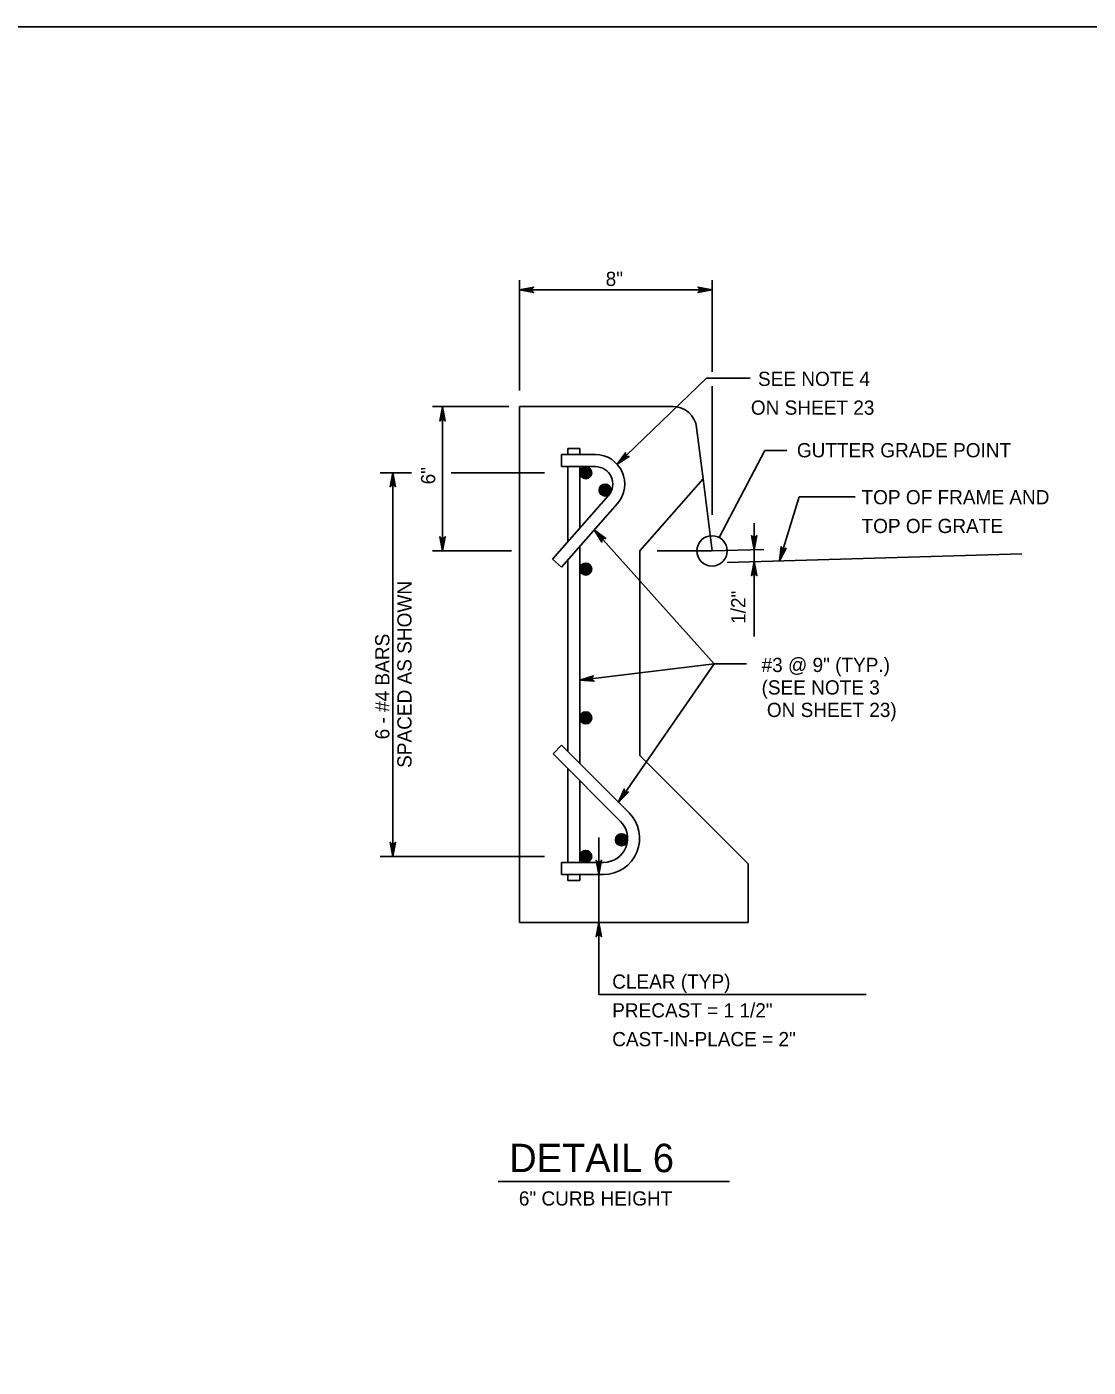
# Model space of a CAD drawing. Extents: x 2087776 to 2104538, y 970919 to 982612.
# Drawn here: x 2094157 to 2094893, y 971891 to 972819 of the extents above; entities that cross this region are included whole.
import ezdxf

# ---------------------------------------------------------------- set-up
doc = ezdxf.new("R2010")
doc.units = 0
doc.layers.add('1', color=7, linetype='Continuous')

msp = doc.modelspace()

# ---------------------------------------------------------------- linework, layer by layer
at = {"layer": '1'}
for p, q in [((2094498.72, 972643.41), (2094498.72, 972567.09)), ((2094632.06, 972643.41), (2094632.06, 972580.08)), ((2094498.72, 972636.85), (2094632.06, 972636.85)), ((2094632.06, 972570.04), (2094632.06, 972481)), ((2094438.47, 972556.01), (2094491.38, 972556.01)), ((2094445.35, 972456.01), (2094445.35, 972556.01)), ((2094498.72, 972198.65), (2094498.72, 972556.01)), ((2094604.85, 972556.01), (2094498.72, 972556.01)), ((2094625.81, 972506.01), (2094621.39, 972541.41)), ((2094551.28, 972522.68), (2094527.88, 972522.68)), ((2094527.88, 972514.35), (2094527.88, 972522.68)), ((2094540.38, 972526.85), (2094532.05, 972526.85)), ((2094532.05, 972522.68), (2094532.05, 972526.85)), ((2094540.38, 972522.68), (2094540.38, 972526.85)), ((2094636.94, 972465.3), (2094668.65, 972525.63)), ((2094668.65, 972525.63), (2094683.82, 972525.63)), ((2094402.1, 972510.18), (2094423.93, 972510.18)), ((2094410.94, 972510.18), (2094410.94, 972244.47)), ((2094451.41, 972510.18), (2094515.9, 972510.18)), ((2094551.3, 972514.35), (2094527.88, 972514.35)), ((2094532.05, 972462.12), (2094532.05, 972514.35)), ((2094540.38, 972471.64), (2094540.38, 972514.35)), ((2094625.81, 972506.01), (2094582.06, 972456.01)), ((2094632.06, 972456.01), (2094625.81, 972506.01)), ((2094560.33, 972494.44), (2094521.61, 972450.19)), ((2094692.5, 972493.5), (2094678.76, 972449.1)), ((2094692.5, 972493.5), (2094731.15, 972493.5)), ((2094566.59, 972488.94), (2094527.88, 972444.7)), ((2094661.28, 972475.2), (2094661.28, 972396.67)), ((2094550.5, 972470.56), (2094633.54, 972377.82)), ((2094438.47, 972456.01), (2094493.09, 972456.01)), ((2094540.38, 972308.87), (2094540.38, 972458.99)), ((2094582.06, 972314.33), (2094582.06, 972456.01)), ((2094594.13, 972456.01), (2094632.06, 972456.01)), ((2094667.91, 972457.06), (2094632.06, 972456.01)), ((2094632.06, 972456.01), (2094632.06, 972456.01)), ((2094846.64, 972454.03), (2094642.6, 972448.03)), ((2094527.88, 972444.7), (2094521.61, 972450.19)), ((2094532.05, 972317.2), (2094532.05, 972449.47)), ((2094633.54, 972377.82), (2094540.38, 972366.42)), ((2094567.24, 972282.01), (2094633.54, 972377.82)), ((2094633.54, 972377.82), (2094655.85, 972377.82)), ((2094527.88, 972321.37), (2094521.99, 972315.48)), ((2094568.74, 972268.73), (2094521.99, 972315.48)), ((2094574.59, 972274.65), (2094527.88, 972321.37)), ((2094657.06, 972239.33), (2094582.06, 972314.33)), ((2094532.05, 972240.31), (2094532.05, 972305.42)), ((2094540.38, 972240.31), (2094540.38, 972297.09)), ((2094553.58, 972257.52), (2094553.58, 972148.76)), ((2094402.1, 972244.47), (2094515.9, 972244.47)), ((2094556.96, 972240.31), (2094527.88, 972240.31)), ((2094527.88, 972231.98), (2094527.88, 972240.31)), ((2094556.92, 972231.98), (2094527.88, 972231.98)), ((2094532.05, 972227.81), (2094532.05, 972231.98)), ((2094540.38, 972227.81), (2094540.38, 972231.98)), ((2094657.06, 972198.65), (2094657.06, 972239.33)), ((2094532.05, 972227.81), (2094540.38, 972227.81)), ((2094657.06, 972198.65), (2094498.72, 972198.65)), ((2094553.58, 972148.76), (2094738.83, 972148.76)), ((2094484, 972019.4), (2094644.24, 972019.4))]:
    msp.add_line(p, q, dxfattribs=at)
for points in [[(2096000.74, 970968.55), (2096000.74, 972818.94), (2093422, 972818.94), (2093422, 970968.55), (2096000.74, 970968.55), (2096000.74, 971055.03), (2095344.57, 971055.03), (2095344.57, 971267.23), (2096000.74, 971267.23), (2096000.74, 971362.25), (2095344.57, 971362.25), (2095344.57, 970968.55), (2095603.11, 970968.55), (2095603.11, 971055.03), (2095603.11, 970968.55), (2095855.73, 970968.55), (2095855.73, 971055.03), (2095855.73, 971014.62), (2096000.74, 971014.62)], [(2094498.72, 972636.85), (2094508.5, 972638.68), (2094508.13, 972638.42), (2094507.75, 972638.16), (2094507.55, 972637.83), (2094507.36, 972637.5), (2094507.3, 972637.18), (2094507.25, 972636.85), (2094507.3, 972636.52), (2094507.36, 972636.19), (2094507.55, 972635.86), (2094507.75, 972635.54), (2094508.13, 972635.27), (2094508.5, 972635.01), (2094498.72, 972636.85), (2094508.13, 972635.27), (2094507.75, 972635.54), (2094498.72, 972636.85), (2094507.55, 972635.86), (2094507.36, 972636.19), (2094498.72, 972636.85), (2094507.3, 972636.52), (2094507.25, 972636.85), (2094498.72, 972636.85), (2094507.3, 972637.18), (2094507.36, 972637.5), (2094498.72, 972636.85), (2094507.55, 972637.83), (2094507.75, 972638.16), (2094498.72, 972636.85), (2094508.13, 972638.42)], [(2094632.06, 972636.85), (2094622.27, 972635.01), (2094622.65, 972635.27), (2094623.03, 972635.54), (2094623.22, 972635.86), (2094623.41, 972636.19), (2094623.47, 972636.52), (2094623.53, 972636.85), (2094623.47, 972637.18), (2094623.41, 972637.5), (2094623.22, 972637.83), (2094623.03, 972638.16), (2094622.65, 972638.42), (2094622.27, 972638.68), (2094632.06, 972636.85), (2094622.65, 972638.42), (2094623.03, 972638.16), (2094632.06, 972636.85), (2094623.22, 972637.83), (2094623.41, 972637.5), (2094632.06, 972636.85), (2094623.47, 972637.18), (2094623.53, 972636.85), (2094632.06, 972636.85), (2094623.47, 972636.52), (2094623.41, 972636.19), (2094632.06, 972636.85), (2094623.22, 972635.86), (2094623.03, 972635.54), (2094632.06, 972636.85), (2094622.65, 972635.27)], [(2094566.37, 972515.97), (2094628.15, 972575.56), (2094658.5, 972575.56)], [(2094445.35, 972555.69), (2094447.19, 972545.9), (2094446.93, 972546.28), (2094446.67, 972546.66), (2094446.34, 972546.85), (2094446.01, 972547.05), (2094445.68, 972547.1), (2094445.35, 972547.16), (2094445.03, 972547.1), (2094444.7, 972547.05), (2094444.37, 972546.85), (2094444.04, 972546.66), (2094443.78, 972546.28), (2094443.52, 972545.9), (2094445.35, 972555.69), (2094443.78, 972546.28), (2094444.04, 972546.66), (2094445.35, 972555.69), (2094444.37, 972546.85), (2094444.7, 972547.05), (2094445.35, 972555.69), (2094445.03, 972547.1), (2094445.35, 972547.16), (2094445.35, 972555.69), (2094445.68, 972547.1), (2094446.01, 972547.05), (2094445.35, 972555.69), (2094446.34, 972546.85), (2094446.67, 972546.66), (2094445.35, 972555.69), (2094446.93, 972546.28)], [(2094566.37, 972515.97), (2094572.1, 972524.02), (2094572.01, 972523.57), (2094571.92, 972523.13), (2094572.01, 972522.76), (2094572.1, 972522.39), (2094572.28, 972522.12), (2094572.47, 972521.84), (2094572.73, 972521.65), (2094573, 972521.45), (2094573.36, 972521.35), (2094573.73, 972521.25), (2094574.18, 972521.32), (2094574.63, 972521.4), (2094566.37, 972515.97), (2094574.18, 972521.32), (2094573.73, 972521.25), (2094566.37, 972515.97), (2094573.36, 972521.35), (2094573, 972521.45), (2094566.37, 972515.97), (2094572.73, 972521.65), (2094572.47, 972521.84), (2094566.37, 972515.97), (2094572.28, 972522.12), (2094572.1, 972522.39), (2094566.37, 972515.97), (2094572.01, 972522.76), (2094571.92, 972523.13), (2094566.37, 972515.97), (2094572.01, 972523.57)], [(2094410.94, 972510.18), (2094412.77, 972500.39), (2094412.51, 972500.77), (2094412.25, 972501.14), (2094411.92, 972501.34), (2094411.6, 972501.53), (2094411.27, 972501.59), (2094410.94, 972501.65), (2094410.61, 972501.59), (2094410.28, 972501.53), (2094409.96, 972501.34), (2094409.63, 972501.14), (2094409.37, 972500.77), (2094409.1, 972500.39), (2094410.94, 972510.18), (2094409.37, 972500.77), (2094409.63, 972501.14), (2094410.94, 972510.18), (2094409.96, 972501.34), (2094410.28, 972501.53), (2094410.94, 972510.18), (2094410.61, 972501.59), (2094410.94, 972501.65), (2094410.94, 972510.18), (2094411.27, 972501.59), (2094411.6, 972501.53), (2094410.94, 972510.18), (2094411.92, 972501.34), (2094412.25, 972501.14), (2094410.94, 972510.18), (2094412.51, 972500.77)], [(2094445.35, 972456.01), (2094443.52, 972465.79), (2094443.78, 972465.41), (2094444.04, 972465.04), (2094444.37, 972464.84), (2094444.7, 972464.65), (2094445.03, 972464.59), (2094445.35, 972464.54), (2094445.68, 972464.59), (2094446.01, 972464.65), (2094446.34, 972464.84), (2094446.67, 972465.04), (2094446.93, 972465.41), (2094447.19, 972465.79), (2094445.35, 972456.01), (2094446.93, 972465.41), (2094446.67, 972465.04), (2094445.35, 972456.01), (2094446.34, 972464.84), (2094446.01, 972464.65), (2094445.35, 972456.01), (2094445.68, 972464.59), (2094445.35, 972464.54), (2094445.35, 972456.01), (2094445.03, 972464.59), (2094444.7, 972464.65), (2094445.35, 972456.01), (2094444.37, 972464.84), (2094444.04, 972465.04), (2094445.35, 972456.01), (2094443.78, 972465.41)], [(2094550.5, 972470.56), (2094558.46, 972464.57), (2094558.01, 972464.67), (2094557.56, 972464.77), (2094557.19, 972464.7), (2094556.82, 972464.62), (2094556.54, 972464.44), (2094556.26, 972464.26), (2094556.05, 972464), (2094555.85, 972463.73), (2094555.74, 972463.37), (2094555.62, 972463), (2094555.69, 972462.55), (2094555.75, 972462.1), (2094550.5, 972470.56), (2094555.69, 972462.55), (2094555.62, 972463), (2094550.5, 972470.56), (2094555.74, 972463.37), (2094555.85, 972463.73), (2094550.5, 972470.56), (2094556.05, 972464), (2094556.26, 972464.26), (2094550.5, 972470.56), (2094556.54, 972464.44), (2094556.82, 972464.62), (2094550.5, 972470.56), (2094557.19, 972464.7), (2094557.56, 972464.77), (2094550.5, 972470.56), (2094558.01, 972464.67)], [(2094661.28, 972456.86), (2094659.45, 972466.65), (2094659.71, 972466.27), (2094659.97, 972465.9), (2094660.3, 972465.7), (2094660.62, 972465.51), (2094660.95, 972465.45), (2094661.28, 972465.39), (2094661.61, 972465.45), (2094661.94, 972465.51), (2094662.26, 972465.7), (2094662.59, 972465.9), (2094662.85, 972466.27), (2094663.12, 972466.65), (2094661.28, 972456.86), (2094662.85, 972466.27), (2094662.59, 972465.9), (2094661.28, 972456.86), (2094662.26, 972465.7), (2094661.94, 972465.51), (2094661.28, 972456.86), (2094661.61, 972465.45), (2094661.28, 972465.39), (2094661.28, 972456.86), (2094660.95, 972465.45), (2094660.62, 972465.51), (2094661.28, 972456.86), (2094660.3, 972465.7), (2094659.97, 972465.9), (2094661.28, 972456.86), (2094659.71, 972466.27)], [(2094678.76, 972449.1), (2094679.9, 972458.99), (2094680.04, 972458.55), (2094680.18, 972458.11), (2094680.43, 972457.83), (2094680.69, 972457.55), (2094680.99, 972457.4), (2094681.28, 972457.24), (2094681.61, 972457.2), (2094681.94, 972457.16), (2094682.32, 972457.25), (2094682.69, 972457.34), (2094683.05, 972457.62), (2094683.41, 972457.9), (2094678.76, 972449.1), (2094683.05, 972457.62), (2094682.69, 972457.34), (2094678.76, 972449.1), (2094682.32, 972457.25), (2094681.94, 972457.16), (2094678.76, 972449.1), (2094681.61, 972457.2), (2094681.28, 972457.24), (2094678.76, 972449.1), (2094680.99, 972457.4), (2094680.69, 972457.55), (2094678.76, 972449.1), (2094680.43, 972457.83), (2094680.18, 972458.11), (2094678.76, 972449.1), (2094680.04, 972458.55)], [(2094661.28, 972448.58), (2094663.12, 972438.8), (2094662.85, 972439.17), (2094662.59, 972439.55), (2094662.26, 972439.74), (2094661.94, 972439.94), (2094661.61, 972440), (2094661.28, 972440.05), (2094660.95, 972440), (2094660.62, 972439.94), (2094660.3, 972439.74), (2094659.97, 972439.55), (2094659.71, 972439.17), (2094659.45, 972438.8), (2094661.28, 972448.58), (2094659.71, 972439.17), (2094659.97, 972439.55), (2094661.28, 972448.58), (2094660.3, 972439.74), (2094660.62, 972439.94), (2094661.28, 972448.58), (2094660.95, 972440), (2094661.28, 972440.05), (2094661.28, 972448.58), (2094661.61, 972440), (2094661.94, 972439.94), (2094661.28, 972448.58), (2094662.26, 972439.74), (2094662.59, 972439.55), (2094661.28, 972448.58), (2094662.85, 972439.17)], [(2094540.38, 972366.42), (2094549.87, 972369.43), (2094549.52, 972369.12), (2094549.18, 972368.82), (2094549.03, 972368.47), (2094548.88, 972368.12), (2094548.86, 972367.79), (2094548.84, 972367.45), (2094548.94, 972367.13), (2094549.04, 972366.82), (2094549.27, 972366.51), (2094549.5, 972366.21), (2094549.91, 972366), (2094550.31, 972365.78), (2094540.38, 972366.42), (2094549.91, 972366), (2094549.5, 972366.21), (2094540.38, 972366.42), (2094549.27, 972366.51), (2094549.04, 972366.82), (2094540.38, 972366.42), (2094548.94, 972367.13), (2094548.84, 972367.45), (2094540.38, 972366.42), (2094548.86, 972367.79), (2094548.88, 972368.12), (2094540.38, 972366.42), (2094549.03, 972368.47), (2094549.18, 972368.82), (2094540.38, 972366.42), (2094549.52, 972369.12)], [(2094567.24, 972282.01), (2094571.26, 972291.11), (2094571.26, 972290.65), (2094571.27, 972290.2), (2094571.43, 972289.85), (2094571.59, 972289.5), (2094571.83, 972289.27), (2094572.07, 972289.04), (2094572.37, 972288.9), (2094572.67, 972288.76), (2094573.05, 972288.74), (2094573.43, 972288.71), (2094573.86, 972288.87), (2094574.29, 972289.04), (2094567.24, 972282.01), (2094573.86, 972288.87), (2094573.43, 972288.71), (2094567.24, 972282.01), (2094573.05, 972288.74), (2094572.67, 972288.76), (2094567.24, 972282.01), (2094572.37, 972288.9), (2094572.07, 972289.04), (2094567.24, 972282.01), (2094571.83, 972289.27), (2094571.59, 972289.5), (2094567.24, 972282.01), (2094571.43, 972289.85), (2094571.27, 972290.2), (2094567.24, 972282.01), (2094571.26, 972290.65)], [(2094410.94, 972244.47), (2094409.1, 972254.26), (2094409.37, 972253.88), (2094409.63, 972253.5), (2094409.96, 972253.31), (2094410.28, 972253.12), (2094410.61, 972253.06), (2094410.94, 972253), (2094411.27, 972253.06), (2094411.6, 972253.12), (2094411.92, 972253.31), (2094412.25, 972253.5), (2094412.51, 972253.88), (2094412.77, 972254.26), (2094410.94, 972244.47), (2094412.51, 972253.88), (2094412.25, 972253.5), (2094410.94, 972244.47), (2094411.92, 972253.31), (2094411.6, 972253.12), (2094410.94, 972244.47), (2094411.27, 972253.06), (2094410.94, 972253), (2094410.94, 972244.47), (2094410.61, 972253.06), (2094410.28, 972253.12), (2094410.94, 972244.47), (2094409.96, 972253.31), (2094409.63, 972253.5), (2094410.94, 972244.47), (2094409.37, 972253.88)], [(2094553.58, 972231.98), (2094551.75, 972241.76), (2094552.01, 972241.38), (2094552.27, 972241.01), (2094552.6, 972240.81), (2094552.93, 972240.62), (2094553.26, 972240.56), (2094553.58, 972240.51), (2094553.91, 972240.56), (2094554.24, 972240.62), (2094554.57, 972240.81), (2094554.9, 972241.01), (2094555.16, 972241.38), (2094555.42, 972241.76), (2094553.58, 972231.98), (2094555.16, 972241.38), (2094554.9, 972241.01), (2094553.58, 972231.98), (2094554.57, 972240.81), (2094554.24, 972240.62), (2094553.58, 972231.98), (2094553.91, 972240.56), (2094553.58, 972240.51), (2094553.58, 972231.98), (2094553.26, 972240.56), (2094552.93, 972240.62), (2094553.58, 972231.98), (2094552.6, 972240.81), (2094552.27, 972241.01), (2094553.58, 972231.98), (2094552.01, 972241.38)], [(2094553.58, 972198.65), (2094551.75, 972188.86), (2094552.01, 972189.24), (2094552.27, 972189.61), (2094552.6, 972189.81), (2094552.93, 972190), (2094553.26, 972190.06), (2094553.58, 972190.11), (2094553.91, 972190.06), (2094554.24, 972190), (2094554.57, 972189.81), (2094554.9, 972189.61), (2094555.16, 972189.24), (2094555.42, 972188.86), (2094553.58, 972198.65), (2094555.16, 972189.24), (2094554.9, 972189.61), (2094553.58, 972198.65), (2094554.57, 972189.81), (2094554.24, 972190), (2094553.58, 972198.65), (2094553.91, 972190.06), (2094553.58, 972190.11), (2094553.58, 972198.65), (2094553.26, 972190.06), (2094552.93, 972190), (2094553.58, 972198.65), (2094552.6, 972189.81), (2094552.27, 972189.61), (2094553.58, 972198.65), (2094552.01, 972189.24)]]:
    msp.add_lwpolyline(points, dxfattribs=at)
for centre, radius in [((2094544.54, 972510.18), 4.17), ((2094544.54, 972510.18), 3.87), ((2094544.54, 972510.18), 3.58), ((2094544.54, 972510.18), 3.28), ((2094544.54, 972510.18), 2.98), ((2094544.54, 972510.18), 2.69), ((2094544.54, 972510.18), 2.39), ((2094544.54, 972510.18), 2.1), ((2094544.54, 972510.18), 1.8), ((2094544.54, 972510.18), 1.5), ((2094544.54, 972510.18), 1.21), ((2094544.54, 972510.18), 0.912), ((2094544.54, 972510.18), 0.616), ((2094544.54, 972510.18), 0.32), ((2094557.92, 972498.15), 4.17), ((2094557.92, 972498.15), 3.87), ((2094557.92, 972498.15), 3.58), ((2094557.92, 972498.15), 3.28), ((2094557.92, 972498.15), 2.98), ((2094557.92, 972498.15), 2.69), ((2094557.92, 972498.15), 2.39), ((2094557.92, 972498.15), 2.1), ((2094557.92, 972498.15), 1.8), ((2094557.92, 972498.15), 1.5), ((2094557.92, 972498.15), 1.21), ((2094557.92, 972498.15), 0.912), ((2094557.92, 972498.15), 0.616), ((2094557.92, 972498.15), 0.32), ((2094632.06, 972456.01), 10.5), ((2094544.54, 972443.44), 4.17), ((2094544.54, 972443.44), 3.87), ((2094544.54, 972443.44), 3.58), ((2094544.54, 972443.44), 3.28), ((2094544.54, 972443.44), 2.98), ((2094544.54, 972443.44), 2.69), ((2094544.54, 972443.44), 2.39), ((2094544.54, 972443.44), 2.1), ((2094544.54, 972443.44), 1.8), ((2094544.54, 972443.44), 1.5), ((2094544.54, 972443.44), 1.21), ((2094544.54, 972443.44), 0.912), ((2094544.54, 972443.44), 0.616), ((2094544.54, 972443.44), 0.32), ((2094544.54, 972340.38), 4.17), ((2094544.54, 972340.38), 3.87), ((2094544.54, 972340.38), 3.58), ((2094544.54, 972340.38), 3.28), ((2094544.54, 972340.38), 2.98), ((2094544.54, 972340.38), 2.69), ((2094544.54, 972340.38), 2.39), ((2094544.54, 972340.38), 2.1), ((2094544.54, 972340.38), 1.8), ((2094544.54, 972340.38), 1.5), ((2094544.54, 972340.38), 1.21), ((2094544.54, 972340.38), 0.912), ((2094544.54, 972340.38), 0.616), ((2094544.54, 972340.38), 0.32), ((2094569.36, 972255.98), 4.17), ((2094569.36, 972255.98), 3.87), ((2094569.36, 972255.98), 3.58), ((2094569.36, 972255.98), 3.28), ((2094569.36, 972255.98), 2.98), ((2094569.36, 972255.98), 2.69), ((2094569.36, 972255.98), 2.39), ((2094569.36, 972255.98), 2.1), ((2094544.54, 972244.47), 4.17), ((2094569.36, 972255.98), 1.8), ((2094569.36, 972255.98), 1.5), ((2094569.36, 972255.98), 1.21), ((2094569.36, 972255.98), 0.912), ((2094569.36, 972255.98), 0.616), ((2094569.36, 972255.98), 0.32), ((2094544.54, 972244.47), 3.87), ((2094544.54, 972244.47), 3.58), ((2094544.54, 972244.47), 3.28), ((2094544.54, 972244.47), 2.98), ((2094544.54, 972244.47), 2.69), ((2094544.54, 972244.47), 2.39), ((2094544.54, 972244.47), 2.1), ((2094544.54, 972244.47), 1.8), ((2094544.54, 972244.47), 1.5), ((2094544.54, 972244.47), 1.21), ((2094544.54, 972244.47), 0.912), ((2094544.54, 972244.47), 0.616), ((2094544.54, 972244.47), 0.32)]:
    msp.add_circle(centre, radius, dxfattribs=at)
for centre, radius, start, end in [((2094604.85, 972539.34), 16.67, 7.12184, 90), ((2094551.28, 972502.34), 20.34, 318.81225, 90), ((2094551.3, 972502.35), 12, 318.81225, 90), ((2094556.92, 972256.98), 25, 270, 45), ((2094556.96, 972256.96), 16.65, 270, 45)]:
    msp.add_arc(centre, radius, start, end, dxfattribs=at)

# ---------------------------------------------------------------- texts
for s, height, rotation, p in [('8"', 9.843, 360, (2094558.38, 972639.46)), ('6"', 9.843, 90, (2094440.28, 972502.08)), ('SPACED AS SHOWN', 9.8425, 90, (2094423.88, 972305.76)), ('1/2"', 9.843, 90, (2094655.16, 972405.45)), ('6 - #4 BARS', 9.8425, 90, (2094408.53, 972325.49))]:
    msp.add_text(s, height=height, rotation=rotation, dxfattribs=at).set_placement(p)
for s, height, p in [('SEE NOTE 4', 9.843, (2094663.89, 972570.24)), ('ON SHEET 23', 9.8425, (2094658.96, 972550.32)), ('GUTTER GRADE POINT', 9.8425, (2094690.84, 972520.82)), ('TOP OF FRAME AND', 9.8425, (2094735.64, 972488.29)), ('TOP OF GRATE', 9.8425, (2094735.64, 972468.37)), ('#3 @ 9" (TYP.)', 9.8425, (2094666.38, 972372.14)), ('(SEE NOTE 3', 9.8425, (2094666.38, 972356.56)), (' ON SHEET 23) ', 9.8425, (2094666.38, 972340.98)), ('CLEAR (TYP)', 9.8425, (2094562.9, 972152.85)), ('PRECAST = 1 1/2"', 9.8425, (2094562.9, 972132.92)), ('CAST-IN-PLACE = 2"', 9.8425, (2094562.9, 972113)), ('DETAIL 6', 19.685, (2094491.57, 972025.8)), ('6" CURB HEIGHT', 9.8425, (2094498.22, 972002.67))]:
    msp.add_text(s, height=height, dxfattribs=at).set_placement(p)

doc.saveas('drawing.dxf')
